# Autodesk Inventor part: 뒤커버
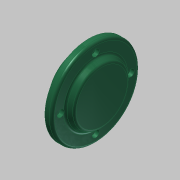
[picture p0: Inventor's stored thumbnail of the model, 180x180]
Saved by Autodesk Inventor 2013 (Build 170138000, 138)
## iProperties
Created: 2015-11
Part Number: 뒤커버
Material: 일반
Document SubType Name: Modeling
Designer: mduedu
Density: 2.71 g/cm^3
Author: mduedu
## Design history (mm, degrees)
sketch "스케치1"
  geometry: C1 r 50 at (0, 0); 1 further point
  constraints: 1 centre point, 1 coincident
  dimensions: "d42" = 100 diameter of C1
extrude "돌출1" new body sketch "스케치1" distance "d3" = 8; taper "d4" = 0 deg
sketch "스케치2"
  geometry: C1 r 35 at (0, 0); 1 further point
  constraints: 1 centre point, 1 coincident
  dimensions: "d5" = 70 diameter of C1
extrude "돌출2" join sketch "스케치2" distance "d6" = 7; taper "d7" = -30 deg
sketch "스케치5" dims "d44" = 80
  geometry: 3 further points
  constraints: 2 vertical alignment, 1 coincident, 2 other
hole "구멍3" sketch "스케치5" at (0, 40) diameter "d45" = 4.5; stored, may be unused: countersink angle "d49" = 90 deg, drill point angle "d51" = 118 deg; dims "d46" = 6, "d47" = 8, "d48" = 4.4, "d50" = 8
sketch "스케치4"
  geometry: C1 r 35 at (0, 0); 1 further point
  constraints: 1 centre point, 1 coincident
  dimensions: "d21" = 70 diameter of C1
extrude "돌출3" join sketch "스케치4" distance "d23" = 12; taper "d24" = 0 deg
hole "구멍2" diameter "d27" = 30; stored, may be unused: countersink angle "d31" = 90 deg, drill point angle "d33" = 0 deg; dims "d25" = 10, "d26" = 10, "d28" = 6, "d29" = 40, "d30" = 12, "d32" = 15
fillet "모깎기3" dims "d36" = 3
fillet "모깎기4" dims "d37" = 3
fillet "모깎기5" dims "d38" = 0.3
chamfer "모따기1" distance "d39" = 1; stored, may be unused: second distance "d40" = 2, angle "d41" = 45 deg
node "솔리드1"
pattern_circular "원형 패턴2" dims angle "d53" = 360 deg
